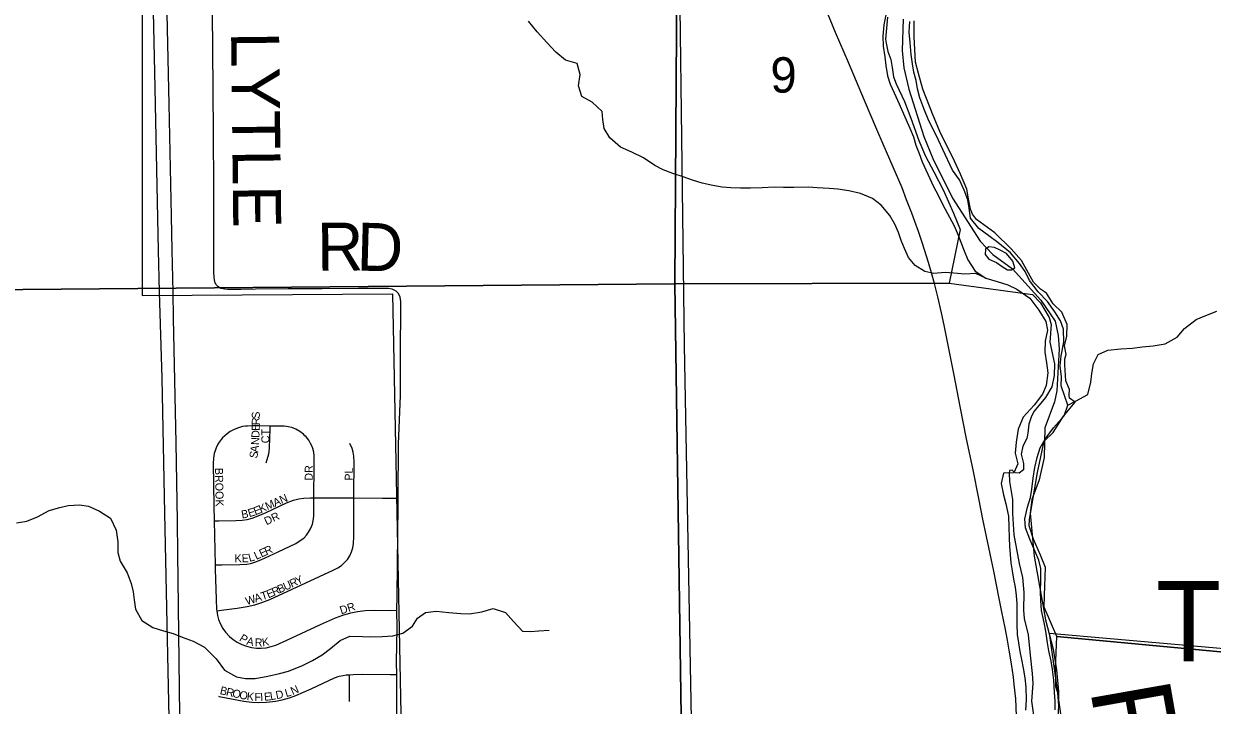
# Model space of a CAD drawing. Extents: x 0 to 680, y 0 to 440.
# Drawn here: x 457.85 to 482.64, y 358.36 to 372.58 of the extents above; entities that cross this region are included whole.
import ezdxf

# ---------------------------------------------------------------- set-up
doc = ezdxf.new("R2010")
doc.units = 0
for name, color, linetype in [('GM_X_City_Street', 7, 'Continuous'), ('GM_X_City_Street_Text', 7, 'Continuous'), ('GM_X_Corporation', 7, 'Continuous'), ('GM_X_Corporation_Text', 7, 'Continuous'), ('GM_X_County_Road', 7, 'Continuous'), ('GM_X_Interstate_Route', 7, 'Continuous'), ('GM_X_Major_River', 7, 'Continuous'), ('GM_X_Major_River_Text', 7, 'Continuous'), ('GM_X_Minor_River', 7, 'Continuous'), ('GM_X_Rail_Line', 7, 'Continuous'), ('GM_X_Section', 7, 'Continuous'), ('GM_X_Section_Text', 7, 'Continuous'), ('GM_X_Township', 7, 'Continuous'), ('GM_X_Township_Road', 7, 'Continuous'), ('GM_X_Township_Road_Text', 7, 'Continuous')]:
    doc.layers.add(name, color=color, linetype=linetype)

msp = doc.modelspace()

# ---------------------------------------------------------------- linework, layer by layer
at = {"layer": 'GM_X_City_Street'}
for points in [[(462.993, 364.188), (462.76, 364.192), (462.631, 364.192), (462.518, 364.188), (462.474, 364.185), (462.416, 364.177), (462.332, 364.154), (462.238, 364.117), (462.159, 364.075), (462.095, 364.027), (462, 363.941)], [(462.911, 363.424), (462.932, 363.49), (462.966, 363.606), (462.974, 363.654), (462.981, 363.736), (462.992, 364.123), (462.993, 364.188)], [(463.904, 362.688), (463.904, 362.811), (463.91, 363.238), (463.909, 363.568), (463.901, 363.646), (463.88, 363.722), (463.859, 363.774), (463.836, 363.825), (463.796, 363.893), (463.741, 363.965), (463.718, 363.987), (463.684, 364.019), (463.612, 364.072), (463.524, 364.122), (463.441, 364.155), (463.37, 364.173), (463.333, 364.179), (463.286, 364.183), (463.211, 364.185), (462.993, 364.188)], [(462, 363.941), (461.967, 363.906), (461.925, 363.854), (461.898, 363.811), (461.862, 363.732), (461.849, 363.693), (461.825, 363.615), (461.807, 363.517), (461.8, 363.406), (461.818, 362.525), (461.824, 362.209)], [(464.74, 362.69), (464.74, 362.757), (464.742, 363.436), (464.739, 363.558), (464.726, 363.646), (464.703, 363.722), (464.656, 363.823)], [(461.824, 362.209), (461.923, 362.209), (462.273, 362.216), (462.405, 362.225), (462.512, 362.242), (462.615, 362.268), (462.742, 362.313), (462.907, 362.387), (463.33, 362.585), (463.479, 362.643), (463.589, 362.672), (463.696, 362.685), (463.832, 362.691), (463.904, 362.688)], [(461.842, 361.291), (461.985, 361.292), (462.357, 361.3), (462.506, 361.31), (462.58, 361.323), (462.654, 361.342), (462.797, 361.397), (463.158, 361.567), (463.525, 361.741), (463.62, 361.798), (463.691, 361.853), (463.747, 361.909), (463.794, 361.972), (463.832, 362.041), (463.876, 362.144), (463.89, 362.209), (463.9, 362.31), (463.903, 362.446), (463.904, 362.688)], [(461.878, 360.333), (462.023, 360.352), (462.304, 360.39), (462.511, 360.423), (462.672, 360.459), (462.819, 360.505), (462.983, 360.57), (463.45, 360.785), (464.305, 361.179), (464.404, 361.229), (464.478, 361.28), (464.552, 361.347), (464.603, 361.408), (464.651, 361.483), (464.689, 361.564), (464.716, 361.65), (464.731, 361.737), (464.738, 361.876), (464.74, 362.69)], [(463.904, 362.688), (464.605, 362.691), (464.74, 362.69)], [(464.74, 362.69), (465.333, 362.682), (465.592, 362.685), (465.661, 362.686)], [(461.824, 362.209), (461.842, 361.291)], [(461.842, 361.291), (461.844, 361.204), (461.862, 360.569), (461.874, 360.36), (461.878, 360.333)], [(461.878, 360.333), (461.892, 360.239), (461.915, 360.153), (461.949, 360.07), (462.007, 359.962), (462.058, 359.888), (462.142, 359.799), (462.22, 359.736), (462.304, 359.681), (462.402, 359.629), (462.497, 359.594), (462.605, 359.568), (462.705, 359.555), (462.805, 359.554), (462.905, 359.565), (463.014, 359.588), (463.109, 359.62), (463.339, 359.725), (464.045, 360.051), (464.354, 360.189), (464.507, 360.245), (464.674, 360.292), (464.813, 360.32), (464.974, 360.339), (465.159, 360.345), (465.498, 360.344), (465.635, 360.346)], [(461.916, 358.552), (461.927, 358.55), (462.443, 358.451), (462.607, 358.43), (462.75, 358.423), (462.915, 358.429), (463.102, 358.448), (463.243, 358.475), (463.392, 358.516), (463.526, 358.565), (463.846, 358.709), (464.332, 358.934), (464.433, 358.969), (464.511, 358.987), (464.574, 358.996), (464.645, 359.002)], [(464.643, 358.444), (464.645, 358.941), (464.645, 359.002)], [(464.645, 359.002), (464.724, 359.008), (464.917, 359.013), (465.496, 359.007), (465.633, 359.005)]]:
    msp.add_lwpolyline(points, dxfattribs=at)
at = {"layer": 'GM_X_Corporation'}
for points in [[(453.864, 374.17), (460.325, 374.263), (460.325, 366.908), (465.546, 366.947), (465.725, 357.839)], [(479.748, 356.3), (479.247, 359.865), (487.404, 359.153), (486.745, 351.206)]]:
    msp.add_lwpolyline(points, dxfattribs=at)
at = {"layer": 'GM_X_County_Road'}
for points in [[(476.721, 367.602), (476.597, 367.994), (476.514, 368.245), (476.44, 368.458), (476.376, 368.632), (476.268, 368.908), (476.172, 369.154), (475.987, 369.59), (475.78, 370.07), (475.647, 370.377), (475.388, 370.981), (475.053, 371.77), (474.785, 372.394), (474.56, 372.942), (474.436, 373.271), (474.335, 373.574), (474.218, 373.975), (474.139, 374.285), (474.074, 374.586), (474.018, 374.844), (473.993, 374.981), (473.958, 375.278), (473.916, 375.804), (473.81, 377.377)], [(478.562, 358.142), (478.544, 358.496), (478.513, 358.797), (478.494, 358.952), (478.455, 359.225), (478.408, 359.515), (478.37, 359.725), (478.323, 359.979), (478.254, 360.313), (478.198, 360.589), (478.083, 361.158), (477.936, 361.884), (477.859, 362.248), (477.774, 362.679), (477.652, 363.276), (477.519, 363.919), (477.387, 364.598), (477.257, 365.25), (477.195, 365.564), (477.109, 366.016), (477.05, 366.296), (476.997, 366.55), (476.92, 366.887), (476.848, 367.163), (476.787, 367.382), (476.721, 367.602)]]:
    msp.add_lwpolyline(points, dxfattribs=at)
at = {"layer": 'GM_X_Interstate_Route'}
for points in [[(460.898, 357.443), (460.794, 362.37), (460.737, 365.184), (460.68, 366.986), (460.662, 367.847), (460.584, 371.569), (460.497, 375.664), (460.462, 377.154), (460.435, 378.28), (460.349, 382.549), (460.368, 384.377), (460.388, 384.88), (460.504, 386.507)], [(460.932, 368.568), (460.882, 370.901), (460.834, 373.113), (460.774, 376.036), (460.749, 377.157), (460.746, 377.256), (460.681, 380.272), (460.638, 382.331), (460.632, 383.01), (460.634, 383.568), (460.642, 383.985), (460.661, 384.554), (460.681, 384.992), (460.726, 385.713)], [(460.965, 366.982), (460.946, 367.86), (460.932, 368.568)], [(461.067, 361.52), (461.061, 362.205), (461.029, 363.84), (460.973, 366.436), (460.965, 366.982)], [(461.527, 339.928), (461.522, 340.139), (461.493, 341.494), (461.463, 342.92), (461.389, 346.344), (461.383, 346.632), (461.333, 349.599), (461.274, 351.207), (461.229, 353.626), (461.217, 354.284), (461.117, 357.59), (461.072, 360.985), (461.067, 361.52)]]:
    msp.add_lwpolyline(points, dxfattribs=at)
at = {"layer": 'GM_X_Major_River'}
for points in [[(475.843, 372.8), (475.791, 372.56), (475.772, 372.32), (475.78, 372.113), (475.815, 371.891), (475.837, 371.71), (475.866, 371.495), (475.922, 371.32), (476.005, 371.138), (476.113, 370.908), (476.202, 370.698)], [(476.387, 371.744), (476.365, 371.939), (476.344, 372.187), (476.322, 372.401), (476.334, 372.628)], [(479.368, 358.266), (479.365, 358.447), (479.35, 358.628), (479.336, 358.889), (479.307, 359.11), (479.285, 359.285), (479.236, 359.5), (479.207, 359.668), (479.172, 359.909), (479.136, 360.091), (479.082, 360.339), (479.067, 360.547), (479.058, 360.728), (479.07, 360.975), (479.069, 361.216), (479.026, 361.391), (478.836, 361.83), (478.748, 362.066), (478.732, 362.253), (478.791, 362.493), (478.85, 362.699), (478.881, 362.872), (478.906, 363.099), (478.945, 363.325), (478.99, 363.532), (479.055, 363.737), (479.159, 363.916), (479.332, 364.152), (479.552, 364.402), (479.631, 364.627), (479.568, 364.803), (479.493, 365.025), (479.497, 365.212), (479.469, 365.447), (479.488, 365.654), (479.548, 365.94), (479.541, 366.208), (479.478, 366.383), (479.362, 366.573), (479.206, 366.784), (479.011, 366.989), (478.829, 367.227), (478.74, 367.41), (478.623, 367.58), (478.434, 367.798), (478.172, 368.018), (477.981, 368.156), (477.771, 368.308), (477.602, 368.526), (477.573, 368.734), (477.544, 368.909), (477.469, 369.111), (477.367, 369.327), (477.224, 369.525), (477.02, 369.957), (476.931, 370.153), (476.836, 370.356), (476.733, 370.552), (476.626, 370.809), (476.544, 371.032), (476.495, 371.22), (476.465, 371.395), (476.416, 371.57), (476.387, 371.744)], [(476.202, 370.698), (476.335, 370.401), (476.411, 370.219), (476.461, 370.05), (476.53, 369.875), (476.593, 369.7), (476.707, 369.443), (476.828, 369.186), (476.924, 369.003), (477.026, 368.8), (477.257, 368.367), (477.339, 368.171), (477.453, 367.881), (477.541, 367.658), (477.696, 367.42), (477.92, 367.275), (478.153, 367.203), (478.379, 367.131), (478.564, 367.046), (478.834, 366.853), (479.028, 366.607), (479.17, 366.37), (479.206, 366.189), (479.16, 365.956), (479.148, 365.728), (479.183, 365.507), (479.212, 365.299), (479.179, 365.032), (479.101, 364.853), (478.928, 364.623), (478.695, 364.374), (478.596, 364.123), (478.549, 363.849), (478.53, 363.622), (478.585, 363.4), (478.501, 363.215), (478.286, 363.207), (478.241, 362.987), (478.289, 362.752), (478.338, 362.563), (478.392, 362.308), (478.401, 362.08), (478.409, 361.86), (478.411, 361.686), (478.443, 361.337), (478.466, 361.169), (478.495, 360.995), (478.532, 360.827), (478.554, 360.652), (478.564, 360.478), (478.566, 360.304), (478.567, 360.057), (478.576, 359.843), (478.598, 359.668), (478.627, 359.487), (478.664, 359.319), (478.699, 359.138), (478.735, 358.936), (478.757, 358.742), (478.758, 358.481), (478.746, 358.26)], [(478.222, 367.857), (478.103, 367.913), (477.983, 367.929), (477.914, 367.877), (477.905, 367.77), (477.983, 367.668)], [(477.983, 367.668), (478.142, 367.597), (478.26, 367.514), (478.373, 367.445), (478.453, 367.45), (478.521, 367.488), (478.484, 367.63), (478.354, 367.787), (478.222, 367.857)]]:
    msp.add_lwpolyline(points, dxfattribs=at)
at = {"layer": 'GM_X_Minor_River'}
for points in [[(477.92, 367.275), (477.709, 367.367), (477.481, 367.358), (477.254, 367.377), (477.074, 367.388), (476.832, 367.373), (476.646, 367.411), (476.448, 367.536), (476.305, 367.706), (476.223, 367.889), (476.153, 368.058), (476.097, 368.226), (476.021, 368.402), (475.918, 368.578), (475.736, 368.796), (475.558, 368.934), (475.307, 369.04), (475.06, 369.092), (474.834, 369.131), (474.653, 369.142), (474.4, 369.154), (474.219, 369.172), (473.912, 369.165), (473.697, 369.164), (473.51, 369.168), (473.256, 369.16), (473.008, 369.153), (472.801, 369.151), (472.6, 369.155), (472.42, 369.173), (472.227, 369.204), (472.001, 369.256), (471.801, 369.314), (471.609, 369.385), (471.39, 369.457), (471.191, 369.535), (471.013, 369.626), (470.776, 369.786), (470.538, 369.898), (470.299, 370.004), (470.077, 370.203), (469.961, 370.393), (469.932, 370.581), (469.916, 370.748), (469.706, 370.947), (469.495, 371.059), (469.42, 371.288), (469.459, 371.521), (469.397, 371.75), (469.152, 371.822), (468.948, 371.988), (468.766, 372.192), (468.563, 372.411), (468.381, 372.636)], [(479.631, 364.627), (479.807, 364.717), (480.044, 364.845), (480.11, 365.105), (480.134, 365.285), (480.166, 365.484), (480.264, 365.683), (480.467, 365.772), (480.735, 365.799), (480.976, 365.814), (481.178, 365.843), (481.412, 365.864), (481.661, 365.905), (481.911, 366.04), (482.063, 366.224), (482.308, 366.412), (482.477, 366.482), (482.74, 366.583)], [(457.697, 362.168), (457.918, 362.203), (458.141, 362.298), (458.385, 362.427), (458.607, 362.488), (458.775, 362.531), (459.016, 362.546), (459.203, 362.515), (459.434, 362.416), (459.658, 362.264), (459.78, 362.02), (459.814, 361.772), (459.816, 361.551), (459.865, 361.369), (460.006, 361.125), (460.095, 360.903), (460.137, 360.728), (460.154, 360.56), (460.182, 360.366), (460.318, 360.135), (460.541, 359.983), (460.767, 359.918), (460.966, 359.86), (461.159, 359.788), (461.384, 359.703), (461.622, 359.577), (461.864, 359.331), (462.039, 359.099), (462.29, 358.96), (462.476, 358.922), (462.677, 358.924), (462.945, 358.972), (463.187, 359.026), (463.376, 359.075), (463.666, 359.196), (463.876, 359.298), (464.073, 359.414), (464.25, 359.55), (464.454, 359.712), (464.65, 359.808), (464.918, 359.802), (465.091, 359.791), (465.326, 359.799), (465.553, 359.814), (465.762, 359.87), (465.959, 360.012), (466.063, 360.184), (466.233, 360.3), (466.455, 360.328), (466.715, 360.296)], [(466.715, 360.296), (466.968, 360.277), (467.149, 360.272), (467.404, 360.313), (467.646, 360.381), (467.899, 360.302), (468.068, 360.111), (468.257, 359.913), (468.424, 359.902), (468.599, 359.918), (468.813, 359.933)]]:
    msp.add_lwpolyline(points, dxfattribs=at)
at = {"layer": 'GM_X_Rail_Line'}
msp.add_lwpolyline([(471.781, 358.075), (471.631, 365.87), (471.489, 377.251), (471.421, 378.475), (471.363, 379.249), (471.36, 380.305), (471.377, 381.387), (471.353, 382.029), (471.328, 382.533), (471.337, 382.837), (471.302, 383.213), (471.21, 383.853), (471.131, 384.287), (471.05, 384.676), (470.977, 385.036)], dxfattribs=at)
at = {"layer": 'GM_X_Section'}
for points in [[(453.855, 384.689), (471.55, 385.032), (471.435, 367.152), (453.83, 367.001)], [(471.435, 367.152), (471.703, 348.644), (453.515, 348.751), (453.46, 357.576), (453.83, 367.001)]]:
    msp.add_lwpolyline(points, close=True, dxfattribs=at)
for points in [[(475.865, 372.716), (475.83, 372.256), (475.842, 372.176), (475.872, 372.002), (475.935, 371.834), (475.965, 371.667), (475.995, 371.472), (476.046, 371.325), (476.226, 370.961), (476.353, 370.611), (476.524, 370.141), (476.658, 369.818), (476.833, 369.494), (477.039, 369.103), (477.244, 368.632), (477.384, 368.289), (477.156, 367.172), (471.435, 367.152), (471.55, 385.032)], [(487.63, 359.026), (479.401, 359.801), (479.139, 360.413), (479.143, 360.653), (479.161, 361.24), (479.059, 361.496), (478.912, 361.826), (478.824, 362.108), (478.833, 362.241), (478.998, 363.219), (479.137, 363.871), (479.321, 364.054), (479.541, 364.397), (479.786, 364.686), (479.668, 364.769), (479.656, 364.829), (479.665, 364.949), (479.588, 365.131), (479.567, 365.465), (479.57, 365.592), (479.598, 365.684), (479.561, 365.859), (479.612, 366.065), (479.616, 366.305), (479.508, 366.567), (479.324, 366.738), (479.182, 366.961), (479.063, 367.043), (478.912, 367.186), (478.667, 367.644), (478.451, 367.882), (478.104, 368.216), (477.722, 368.496), (477.644, 368.611), (477.599, 368.712), (477.556, 368.927), (477.52, 369.128), (477.392, 369.444), (477.226, 369.807), (476.981, 370.286), (476.821, 370.663), (476.605, 371.214), (476.517, 371.543), (476.455, 371.777), (476.425, 372.305), (476.424, 372.639)], [(471.703, 348.644), (471.435, 367.152), (477.156, 367.172), (478.894, 366.932), (479.058, 366.756), (479.239, 366.452), (479.283, 366.304), (479.256, 365.938), (479.354, 365.489), (479.343, 365.242), (479.298, 365.009), (479.167, 364.785), (478.928, 364.496), (478.873, 364.396), (478.817, 364.231), (478.793, 364.038), (478.778, 363.931), (478.688, 363.772), (478.658, 363.6), (478.708, 363.405), (478.705, 363.278), (478.617, 363.206), (478.531, 363.215), (478.472, 363.269), (478.411, 363.264), (478.404, 363.204), (478.414, 363.03), (478.473, 362.655), (478.475, 362.361), (478.506, 361.92), (478.615, 361.318), (478.683, 361.029), (478.711, 360.715), (478.704, 360.348), (478.721, 360.174), (478.801, 359.832), (478.847, 359.411), (478.886, 359.03), (478.902, 358.816), (478.869, 358.449), (478.928, 358.061)], [(479.441, 358.358), (479.419, 358.626), (479.381, 358.747), (479.377, 358.854), (479.375, 359.121), (479.401, 359.801), (487.63, 359.026), (485.85, 341.665)]]:
    msp.add_lwpolyline(points, dxfattribs=at)
at = {"layer": 'GM_X_Township'}
msp.add_lwpolyline([(476.197, 372.678), (476.171, 372.019), (476.21, 371.661), (476.316, 371.215), (476.626, 370.226), (476.817, 369.771), (477.225, 368.945), (477.802, 368.042), (478.068, 367.764), (478.474, 367.468), (479.067, 366.815), (479.367, 366.378), (479.429, 366.076), (479.449, 365.797), (479.403, 364.925), (479.353, 364.69), (479.151, 364.149), (479.134, 363.534), (479.03, 363.064), (478.88, 362.658), (478.843, 362.368), (478.926, 361.471), (479.166, 360.147), (479.323, 359.533), (479.397, 359.101), (479.435, 358.65), (479.426, 357.943)], dxfattribs=at)
msp.add_lwpolyline([(476.197, 372.678), (476.171, 372.019), (476.21, 371.661), (476.316, 371.215), (476.626, 370.226), (476.817, 369.771), (477.225, 368.945), (477.802, 368.042), (478.068, 367.764), (478.474, 367.468), (479.067, 366.815), (479.367, 366.378), (479.429, 366.076), (479.449, 365.797), (479.403, 364.925), (479.353, 364.69), (479.151, 364.149), (479.134, 363.534), (479.03, 363.064), (478.88, 362.658), (478.843, 362.368), (478.926, 361.471), (479.166, 360.147), (479.323, 359.533), (479.397, 359.101), (479.435, 358.65), (479.426, 357.943)], dxfattribs=at)
at = {"layer": 'GM_X_Township_Road'}
for points in [[(461.919, 367.086), (461.891, 367.108), (461.874, 367.129), (461.857, 367.156), (461.845, 367.178), (461.837, 367.205), (461.828, 367.241), (461.822, 367.291), (461.818, 367.396), (461.82, 368.493), (461.82, 369.2), (461.808, 370.272), (461.801, 371.225), (461.787, 372.824), (461.777, 373.996), (461.779, 374.592), (461.776, 375.293), (461.774, 375.557), (461.77, 375.922), (461.769, 376.328), (461.765, 377.119), (461.765, 377.173)], [(465.661, 362.686), (465.67, 363.808), (465.708, 364.823), (465.712, 365.787), (465.718, 366.597), (465.714, 366.785), (465.7, 366.875), (465.688, 366.908), (465.66, 366.958), (465.619, 366.999), (465.59, 367.018), (465.537, 367.041), (465.458, 367.056), (465.38, 367.059), (464.831, 367.057), (464.076, 367.049), (463.364, 367.047), (462.685, 367.04), (462.378, 367.037), (462.28, 367.038), (462.171, 367.038), (462.103, 367.038), (462.045, 367.043), (462.013, 367.047), (461.985, 367.054), (461.965, 367.059), (461.939, 367.071), (461.919, 367.086)], [(465.635, 360.346), (465.638, 360.645), (465.657, 361.943), (465.659, 362.529), (465.661, 362.686)], [(465.633, 359.005), (465.63, 359.265), (465.638, 359.975), (465.635, 360.346)], [(465.667, 357.948), (465.65, 358.012), (465.638, 358.088), (465.635, 358.177), (465.632, 358.316), (465.634, 358.842), (465.633, 359.005)]]:
    msp.add_lwpolyline(points, dxfattribs=at)

# ---------------------------------------------------------------- texts
at = {"layer": 'GM_X_City_Street_Text'}
for s, height, rotation, p in [('S', 0.167, 90, (462.776, 364.341)), ('E', 0.167, 88.1212, (462.772, 364.085)), ('R', 0.167, 90.0415, (462.776, 364.209)), ('N', 0.167, 87.1781, (462.76, 363.789)), ('D', 0.167, 88.045, (462.767, 363.938)), ('CT', 0.1669, 90, (462.975, 363.828)), ('A', 0.167, 82.7229, (462.74, 363.629)), ('S', 0.167, 79.6438, (462.718, 363.503)), ('BROOK', 0.1669, 271.1685, (461.84, 363.314)), ('DR', 0.1669, 90, (463.88, 363.049)), ('PL', 0.1669, 90, (464.715, 363.049)), ('A', 0.167, 24.0623, (463.094, 362.503)), ('N', 0.167, 23.2502, (463.228, 362.563)), ('B', 0.167, 9.9095, (462.404, 362.258)), ('E', 0.167, 17.0582, (462.556, 362.286)), ('E', 0.167, 21.5892, (462.682, 362.326)), ('K', 0.167, 23.9065, (462.798, 362.372)), ('M', 0.167, 24.0899, (462.933, 362.431)), ('DR', 0.1669, 25.2073, (462.915, 362.116)), ('R', 0.167, 24.3053, (462.915, 361.493)), ('K', 0.167, 0.3935, (462.25, 361.346)), ('E', 0.167, 0.3825, (462.397, 361.347)), ('L', 0.167, 15.3632, (462.561, 361.354)), ('L', 0.167, 24.8123, (462.702, 361.395)), ('E', 0.167, 24.3037, (462.808, 361.444)), ('U', 0.167, 24.9034, (463.309, 360.753)), ('R', 0.167, 24.8922, (463.442, 360.815)), ('Y', 0.167, 24.9133, (463.562, 360.871)), ('A', 0.167, 17.4257, (462.687, 360.508)), ('T', 0.167, 18.0451, (462.829, 360.552)), ('E', 0.167, 22.571, (462.954, 360.594)), ('R', 0.167, 24.8122, (463.069, 360.642)), ('B', 0.167, 24.9183, (463.189, 360.697)), ('W', 0.167, 17.4353, (462.505, 360.45)), ('DR', 0.1669, 17.5239, (464.473, 360.26)), ('P', 0.167, 326.8479, (462.333, 359.722)), ('A', 0.167, 346.4784, (462.488, 359.633)), ('R', 0.167, 358.2716, (462.668, 359.594)), ('K', 0.167, 8.9039, (462.834, 359.592)), ('B', 0.167, 347.1947, (461.933, 358.6)), ('R', 0.167, 347.1947, (462.062, 358.571)), ('N', 0.167, 23.7351, (463.461, 358.574)), ('O', 0.167, 347.1725, (462.191, 358.542)), ('O', 0.167, 347.7635, (462.336, 358.509)), ('K', 0.167, 352.8025, (462.496, 358.475)), ('F', 0.167, 359.8324, (462.664, 358.455)), ('I', 0.167, 1.0134, (462.785, 358.455)), ('E', 0.167, 5.0945, (462.871, 358.457)), ('L', 0.167, 9.4938, (463.002, 358.469)), ('D', 0.167, 11.5358, (463.124, 358.49)), ('L', 0.167, 16.2136, (463.326, 358.533))]:
    msp.add_text(s, height=height, rotation=rotation, dxfattribs=at).set_placement(p)
at = {"layer": 'GM_X_Corporation_Text'}
msp.add_text('TROY', height=1.6689, rotation=0, dxfattribs=at).set_placement((481.467, 359.284))
at = {"layer": 'GM_X_Major_River_Text'}
msp.add_text('River', height=1.6683, rotation=280.0004, dxfattribs=at).set_placement((480.09, 358.701))
at = {"layer": 'GM_X_Section_Text'}
msp.add_text('9', height=0.738, rotation=0, dxfattribs=at).set_placement((473.426, 371.143))
at = {"layer": 'GM_X_Township_Road_Text'}
for s, height, rotation, p in [('LYTLE', 1.0014, 270.6487, (462.176, 372.408)), ('R', 1.001, 0.5386, (463.974, 367.425)), ('D', 1.001, 358.4371, (464.787, 367.433))]:
    msp.add_text(s, height=height, rotation=rotation, dxfattribs=at).set_placement(p)

doc.saveas('drawing.dxf')
